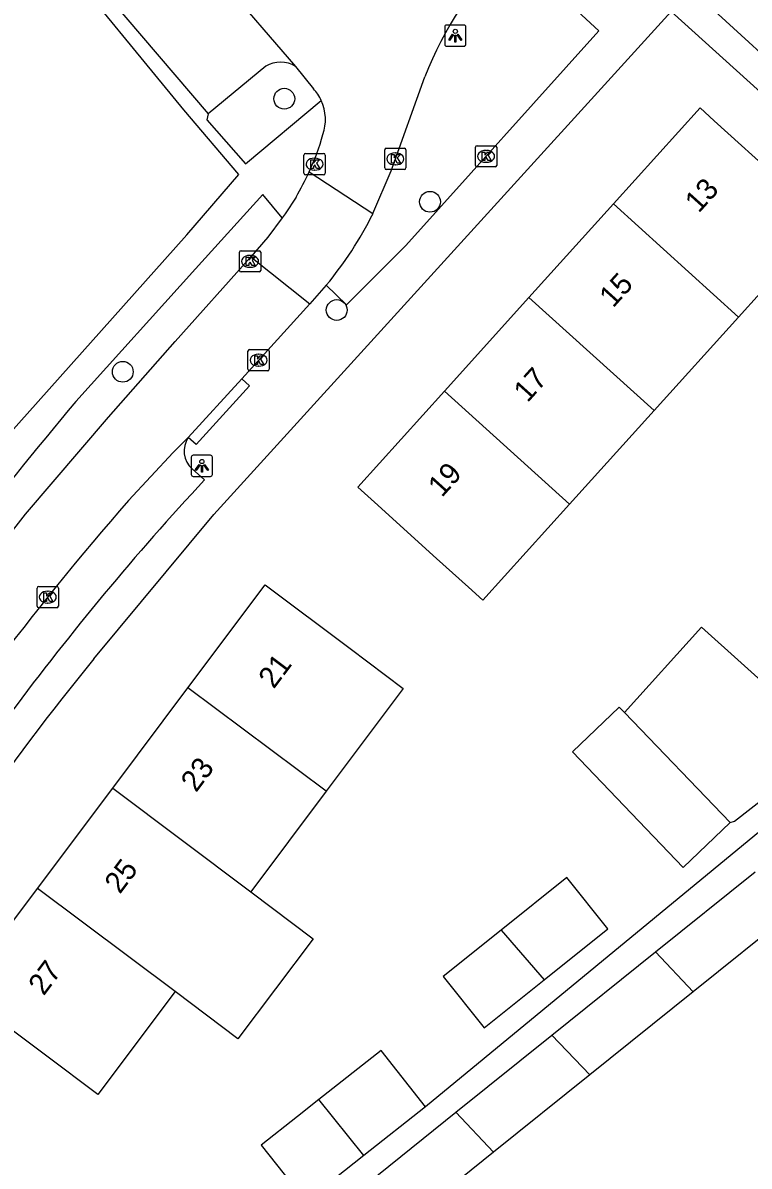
# Model space of a CAD drawing. Extents: x 161882 to 162509, y 381687 to 382379.
# Drawn here: x 162309.9 to 162344.1, y 381823.9 to 381877.6 of the extents above; entities that cross this region are included whole.
import ezdxf

# ---------------------------------------------------------------- set-up
doc = ezdxf.new("R2010")
doc.units = 0
for name, color, linetype in [('IMGEO_Boom', 7, 'Continuous'), ('IMGEO_Kolk', 7, 'Continuous'), ('IMGEO_Lichtpunt', 7, 'Continuous'), ('IMGEO_Pand', 7, 'Continuous'), ('IMGEO_Pand_nummerreeks', 7, 'Continuous'), ('IMGEO_Parkeervlak_open', 7, 'Continuous'), ('IMGEO_Rijbaan_lokaal_open', 7, 'Continuous'), ('IMGEO_Voetpad_open', 7, 'Continuous')]:
    doc.layers.add(name, color=color, linetype=linetype)

msp = doc.modelspace()

# ---------------------------------------------------------------- linework, layer by layer
at = {"layer": 'IMGEO_Boom'}
for centre in [(162322.227, 381874.072), (162329.077, 381869.231), (162324.693, 381864.143), (162314.637, 381861.242)]:
    msp.add_circle(centre, 0.489, dxfattribs=at)
at = {"layer": 'IMGEO_Kolk'}
for p, q in [((162326.947, 381870.819), (162326.947, 381871.671)), ((162327.022, 381871.745), (162327.874, 381871.745)), ((162327.948, 381871.671), (162327.948, 381870.819)), ((162331.214, 381870.94), (162331.214, 381871.792)), ((162331.289, 381871.866), (162332.141, 381871.866)), ((162331.702, 381871.646), (162331.727, 381871.646)), ((162332.215, 381871.792), (162332.215, 381870.94)), ((162323.151, 381870.571), (162323.151, 381871.423)), ((162323.226, 381871.497), (162324.078, 381871.497)), ((162323.639, 381871.277), (162323.664, 381871.277)), ((162324.152, 381871.423), (162324.152, 381870.571)), ((162327.435, 381871.525), (162327.46, 381871.525)), ((162331.725, 381871.086), (162331.7, 381871.086)), ((162324.078, 381870.497), (162323.226, 381870.497)), ((162323.662, 381870.717), (162323.637, 381870.717)), ((162327.874, 381870.745), (162327.022, 381870.745)), ((162327.458, 381870.965), (162327.433, 381870.965)), ((162332.141, 381870.866), (162331.289, 381870.866)), ((162320.119, 381866.006), (162320.119, 381866.858)), ((162320.194, 381866.932), (162321.046, 381866.932)), ((162320.607, 381866.712), (162320.632, 381866.712)), ((162321.12, 381866.858), (162321.12, 381866.006)), ((162321.046, 381865.932), (162320.194, 381865.932)), ((162320.63, 381866.152), (162320.605, 381866.152)), ((162320.52, 381861.36), (162320.52, 381862.212)), ((162320.595, 381862.286), (162321.447, 381862.286)), ((162321.008, 381862.066), (162321.033, 381862.066)), ((162321.521, 381862.212), (162321.521, 381861.36)), ((162321.031, 381861.506), (162321.006, 381861.506)), ((162321.447, 381861.286), (162320.595, 381861.286)), ((162310.685, 381851.154), (162311.537, 381851.154)), ((162310.61, 381850.228), (162310.61, 381851.08)), ((162311.098, 381850.934), (162311.123, 381850.934)), ((162311.611, 381851.08), (162311.611, 381850.228)), ((162311.537, 381850.154), (162310.685, 381850.154)), ((162311.121, 381850.374), (162311.096, 381850.374))]:
    msp.add_line(p, q, dxfattribs=at)
for points in [[(162326.947, 381870.819), (162326.947, 381871.671)], [(162327.022, 381871.745), (162327.874, 381871.745)], [(162327.948, 381871.671), (162327.948, 381870.819)], [(162331.214, 381870.94), (162331.214, 381871.792)], [(162331.289, 381871.866), (162332.141, 381871.866)], [(162331.535, 381871.566), (162331.658, 381871.566), (162331.658, 381871.415), (162331.788, 381871.566), (162331.952, 381871.566), (162331.806, 381871.415), (162331.959, 381871.166), (162331.807, 381871.166), (162331.722, 381871.33), (162331.658, 381871.263), (162331.658, 381871.166), (162331.535, 381871.166), (162331.535, 381871.566)], [(162332.215, 381871.792), (162332.215, 381870.94)], [(162323.151, 381870.571), (162323.151, 381871.423)], [(162323.226, 381871.497), (162324.078, 381871.497)], [(162323.472, 381871.197), (162323.595, 381871.197), (162323.595, 381871.046), (162323.725, 381871.197), (162323.889, 381871.197), (162323.743, 381871.046), (162323.896, 381870.797), (162323.744, 381870.797), (162323.659, 381870.961), (162323.595, 381870.894), (162323.595, 381870.797), (162323.472, 381870.797), (162323.472, 381871.197)], [(162324.152, 381871.423), (162324.152, 381870.571)], [(162327.268, 381871.445), (162327.391, 381871.445), (162327.391, 381871.294), (162327.521, 381871.445), (162327.685, 381871.445), (162327.539, 381871.294), (162327.692, 381871.045), (162327.54, 381871.045), (162327.455, 381871.209), (162327.391, 381871.142), (162327.391, 381871.045), (162327.268, 381871.045), (162327.268, 381871.445)], [(162324.078, 381870.497), (162323.226, 381870.497)], [(162327.874, 381870.745), (162327.022, 381870.745)], [(162332.141, 381870.866), (162331.289, 381870.866)], [(162320.119, 381866.006), (162320.119, 381866.858)], [(162320.194, 381866.932), (162321.046, 381866.932)], [(162321.12, 381866.858), (162321.12, 381866.006)], [(162320.44, 381866.632), (162320.563, 381866.632), (162320.563, 381866.481), (162320.693, 381866.632), (162320.857, 381866.632), (162320.711, 381866.481), (162320.864, 381866.232), (162320.712, 381866.232), (162320.627, 381866.396), (162320.563, 381866.329), (162320.563, 381866.232), (162320.44, 381866.232), (162320.44, 381866.632)], [(162321.046, 381865.932), (162320.194, 381865.932)], [(162320.52, 381861.36), (162320.52, 381862.212)], [(162320.595, 381862.286), (162321.447, 381862.286)], [(162320.841, 381861.986), (162320.964, 381861.986), (162320.964, 381861.835), (162321.094, 381861.986), (162321.258, 381861.986), (162321.112, 381861.835), (162321.265, 381861.586), (162321.113, 381861.586), (162321.028, 381861.75), (162320.964, 381861.683), (162320.964, 381861.586), (162320.841, 381861.586), (162320.841, 381861.986)], [(162321.521, 381862.212), (162321.521, 381861.36)], [(162321.447, 381861.286), (162320.595, 381861.286)], [(162310.685, 381851.154), (162311.537, 381851.154)], [(162310.61, 381850.228), (162310.61, 381851.08)], [(162310.931, 381850.854), (162311.054, 381850.854), (162311.054, 381850.703), (162311.184, 381850.854), (162311.348, 381850.854), (162311.202, 381850.703), (162311.355, 381850.454), (162311.203, 381850.454), (162311.118, 381850.618), (162311.054, 381850.551), (162311.054, 381850.454), (162310.931, 381850.454), (162310.931, 381850.854)], [(162311.611, 381851.08), (162311.611, 381850.228)], [(162311.537, 381850.154), (162310.685, 381850.154)]]:
    msp.add_lwpolyline(points, dxfattribs=at)
for centre, start, end in [((162327.024, 381871.669), 91.552, 178.448), ((162327.024, 381871.669), 91.552, 178.448), ((162327.872, 381871.669), 1.552, 88.448), ((162327.872, 381871.669), 1.552, 88.448), ((162331.291, 381871.79), 91.552, 178.448), ((162331.291, 381871.79), 91.552, 178.448), ((162332.139, 381871.79), 1.552, 88.448), ((162332.139, 381871.79), 1.552, 88.448), ((162323.228, 381871.421), 91.552, 178.448), ((162323.228, 381871.421), 91.552, 178.448), ((162324.076, 381871.421), 1.552, 88.448), ((162324.076, 381871.421), 1.552, 88.448), ((162323.228, 381870.573), 181.552, 268.448), ((162323.228, 381870.573), 181.552, 268.448), ((162324.076, 381870.573), 271.552, 358.448), ((162324.076, 381870.573), 271.552, 358.448), ((162327.024, 381870.821), 181.552, 268.448), ((162327.024, 381870.821), 181.552, 268.448), ((162327.872, 381870.821), 271.552, 358.448), ((162327.872, 381870.821), 271.552, 358.448), ((162331.291, 381870.942), 181.552, 268.448), ((162331.291, 381870.942), 181.552, 268.448), ((162332.139, 381870.942), 271.552, 358.448), ((162332.139, 381870.942), 271.552, 358.448), ((162320.196, 381866.856), 91.552, 178.448), ((162320.196, 381866.856), 91.552, 178.448), ((162321.044, 381866.856), 1.552, 88.448), ((162321.044, 381866.856), 1.552, 88.448), ((162320.196, 381866.008), 181.552, 268.448), ((162320.196, 381866.008), 181.552, 268.448), ((162321.044, 381866.008), 271.552, 358.448), ((162321.044, 381866.008), 271.552, 358.448), ((162320.597, 381862.21), 91.552, 178.448), ((162320.597, 381862.21), 91.552, 178.448), ((162321.445, 381862.21), 1.552, 88.448), ((162321.445, 381862.21), 1.552, 88.448), ((162320.597, 381861.362), 181.552, 268.448), ((162320.597, 381861.362), 181.552, 268.448), ((162321.445, 381861.362), 271.552, 358.448), ((162321.445, 381861.362), 271.552, 358.448), ((162310.687, 381851.078), 91.552, 178.448), ((162310.687, 381851.078), 91.552, 178.448), ((162311.535, 381851.078), 1.552, 88.448), ((162311.535, 381851.078), 1.552, 88.448), ((162310.687, 381850.23), 181.552, 268.448), ((162310.687, 381850.23), 181.552, 268.448), ((162311.535, 381850.23), 271.552, 358.448), ((162311.535, 381850.23), 271.552, 358.448)]:
    msp.add_arc(centre, 0.0765, start, end, dxfattribs=at)
for centre, major_axis, ratio, start_param, end_param in [((162331.701, 381871.366), (-0.387, 0.002), 0.722429, 4.712389, 7.853982), ((162331.726, 381871.366), (-0.39, 0.002), 0.717154, 1.570796, 4.712389), ((162323.638, 381870.997), (-0.387, 0.002), 0.722429, 4.712389, 7.853982), ((162323.663, 381870.997), (-0.39, 0.002), 0.717154, 1.570796, 4.712389), ((162327.434, 381871.245), (-0.387, 0.002), 0.722429, 4.712389, 7.853982), ((162327.459, 381871.245), (-0.39, 0.002), 0.717154, 1.570796, 4.712389), ((162320.606, 381866.432), (-0.387, 0.002), 0.722429, 4.712389, 7.853982), ((162320.631, 381866.432), (-0.39, 0.002), 0.717154, 1.570796, 4.712389), ((162321.007, 381861.786), (-0.387, 0.002), 0.722429, 4.712389, 7.853982), ((162321.032, 381861.786), (-0.39, 0.002), 0.717154, 1.570796, 4.712389), ((162311.097, 381850.654), (-0.387, 0.002), 0.722429, 4.712389, 7.853982), ((162311.122, 381850.654), (-0.39, 0.002), 0.717154, 1.570796, 4.712389)]:
    msp.add_ellipse(centre, major_axis=major_axis, ratio=ratio, start_param=start_param, end_param=end_param, dxfattribs=at)
at = {"layer": 'IMGEO_Lichtpunt'}
for p, q in [((162330.671, 381877.535), (162329.863, 381877.535)), ((162330.671, 381877.535), (162329.863, 381877.535)), ((162329.769, 381877.44), (162329.769, 381876.633)), ((162329.769, 381877.44), (162329.769, 381876.633)), ((162330.765, 381876.633), (162330.765, 381877.44)), ((162330.765, 381876.633), (162330.765, 381877.44)), ((162329.863, 381876.539), (162330.671, 381876.539)), ((162329.863, 381876.539), (162330.671, 381876.539)), ((162317.855, 381857.225), (162317.855, 381856.418)), ((162317.855, 381857.225), (162317.855, 381856.418)), ((162318.757, 381857.32), (162317.949, 381857.32)), ((162318.757, 381857.32), (162317.949, 381857.32)), ((162318.851, 381856.418), (162318.851, 381857.225)), ((162318.851, 381856.418), (162318.851, 381857.225)), ((162317.949, 381856.324), (162318.757, 381856.324)), ((162317.949, 381856.324), (162318.757, 381856.324))]:
    msp.add_line(p, q, dxfattribs=at)
for points in [[(162330.143, 381877.104), (162330.182, 381877.076), (162329.994, 381876.814), (162329.956, 381876.841), (162330.143, 381877.104)], [(162330.245, 381877.056), (162330.292, 381877.056), (162330.292, 381876.734), (162330.245, 381876.734), (162330.245, 381877.056)], [(162330.355, 381877.076), (162330.393, 381877.103), (162330.58, 381876.841), (162330.541, 381876.813), (162330.355, 381877.076)], [(162318.229, 381856.889), (162318.268, 381856.861), (162318.08, 381856.599), (162318.042, 381856.626), (162318.229, 381856.889)], [(162318.331, 381856.841), (162318.378, 381856.841), (162318.378, 381856.519), (162318.331, 381856.519), (162318.331, 381856.841)], [(162318.441, 381856.861), (162318.479, 381856.888), (162318.666, 381856.626), (162318.627, 381856.598), (162318.441, 381856.861)]]:
    msp.add_lwpolyline(points, dxfattribs=at)
for centre in [(162330.268, 381877.238), (162318.354, 381857.023)]:
    msp.add_circle(centre, 0.0994, dxfattribs=at)
for centre, start, end in [((162329.863, 381877.44), 90, 180), ((162329.863, 381877.44), 90, 180), ((162330.671, 381877.44), 0, 90), ((162330.671, 381877.44), 0, 90), ((162329.863, 381876.633), 180, 270), ((162329.863, 381876.633), 180, 270), ((162330.671, 381876.633), 270, 0), ((162330.671, 381876.633), 270, 360), ((162317.949, 381857.225), 90, 180), ((162317.949, 381857.225), 90, 180), ((162318.757, 381857.225), 0, 90), ((162318.757, 381857.225), 0, 90), ((162317.949, 381856.418), 180, 270), ((162317.949, 381856.418), 180, 270), ((162318.757, 381856.418), 270, 0), ((162318.757, 381856.418), 270, 360)]:
    msp.add_arc(centre, 0.0946, start, end, dxfattribs=at)
at = {"layer": 'IMGEO_Pand'}
for points in [[(162337.705, 381869.126), (162341.782, 381873.637), (162342.442, 381873.04), (162345.491, 381870.284), (162347.661, 381868.323), (162343.586, 381863.815)], [(162333.73, 381864.728), (162337.705, 381869.126)], [(162343.586, 381863.815), (162337.705, 381869.126)], [(162329.755, 381860.33), (162333.73, 381864.728)], [(162333.73, 381864.728), (162339.611, 381859.416)], [(162343.586, 381863.815), (162339.611, 381859.416)], [(162335.637, 381855.019), (162331.56, 381850.508), (162330.885, 381851.118), (162329.39, 381852.469), (162326.468, 381855.111), (162325.681, 381855.822), (162329.755, 381860.33)], [(162335.637, 381855.019), (162329.755, 381860.33)], [(162339.611, 381859.416), (162335.637, 381855.019)], [(162317.701, 381846.396), (162321.328, 381851.233), (162325.328, 381848.233), (162327.821, 381846.363), (162324.194, 381841.527)], [(162345.728, 381845.749), (162341.835, 381849.242), (162338.218, 381845.23)], [(162314.163, 381841.68), (162317.701, 381846.396)], [(162324.194, 381841.527), (162317.701, 381846.396)], [(162338.218, 381845.23), (162337.976, 381845.482), (162335.78, 381843.375), (162340.985, 381837.949), (162343.181, 381840.056)], [(162343.181, 381840.056), (162338.218, 381845.23)], [(162343.181, 381840.056), (162343.385, 381840.124), (162347.592, 381843.394)], [(162310.626, 381836.963), (162314.163, 381841.68)], [(162314.163, 381841.68), (162320.657, 381836.81)], [(162324.194, 381841.527), (162320.657, 381836.81)], [(162339.67, 381833.983), (162344.356, 381837.75)], [(162334.447, 381832.668), (162337.444, 381835.066), (162335.512, 381837.481), (162332.417, 381835.005)], [(162317.092, 381832.114), (162313.465, 381827.278), (162310.999, 381829.127), (162306.999, 381832.127), (162310.626, 381836.963)], [(162317.092, 381832.114), (162310.626, 381836.963)], [(162320.657, 381836.81), (162323.58, 381834.6), (162320.051, 381829.895), (162317.092, 381832.114)], [(162346.13, 381835.868), (162341.444, 381832.1)], [(162332.417, 381835.005), (162329.689, 381832.822), (162331.62, 381830.407), (162334.447, 381832.668)], [(162332.417, 381835.005), (162334.447, 381832.668)], [(162334.797, 381830.064), (162339.67, 381833.983)], [(162341.444, 381832.1), (162339.67, 381833.983)], [(162341.444, 381832.1), (162336.598, 381828.204)], [(162330.296, 381826.446), (162334.797, 381830.064)], [(162334.797, 381830.064), (162336.598, 381828.204)], [(162328.871, 381826.707), (162326.779, 381829.352), (162323.856, 381827.039)], [(162336.598, 381828.204), (162332.07, 381824.564)], [(162323.856, 381827.039), (162322.854, 381826.247), (162321.148, 381824.898), (162323.239, 381822.253)], [(162325.971, 381824.413), (162323.856, 381827.039)], [(162325.609, 381822.678), (162330.296, 381826.446)], [(162328.871, 381826.707), (162325.971, 381824.413)], [(162330.296, 381826.446), (162332.07, 381824.564)], [(162325.971, 381824.413), (162323.239, 381822.253)], [(162332.07, 381824.564), (162327.383, 381820.796)]]:
    msp.add_lwpolyline(points, dxfattribs=at)
at = {"layer": 'IMGEO_Parkeervlak_open'}
msp.add_lwpolyline([(162321.355, 381875.602), (162318.649, 381873.357)], dxfattribs=at)
msp.add_arc((162322.046, 381874.442), 1.35, 58.173, 120.7653, dxfattribs=at)
at = {"layer": 'IMGEO_Rijbaan_lokaal_open'}
for points in [[(162315.826, 381883.619), (162322.758, 381875.589)], [(162322.758, 381875.589), (162323.599, 381874.542)], [(162326.398, 381868.679), (162327.245, 381870.683), (162328.833, 381875.105)], [(162323.403, 381870.644), (162326.398, 381868.679)], [(162322.78, 381869.453), (162322.262, 381868.661), (162322.127, 381868.477)], [(162322.127, 381868.477), (162321.455, 381867.563), (162320.649, 381866.638)], [(162303.292, 381845.82), (162306.611, 381850.151), (162310.057, 381854.543), (162313.959, 381859.114), (162317.095, 381862.667), (162320.649, 381866.638)], [(162320.649, 381866.638), (162323.422, 381864.435)], [(162324.203, 381865.309), (162323.422, 381864.435)], [(162323.422, 381864.435), (162320.231, 381860.917)], [(162317.714, 381858.155), (162320.231, 381860.917)], [(162317.714, 381858.155), (162316.997, 381857.442), (162314.904, 381855.188)]]:
    msp.add_lwpolyline(points, dxfattribs=at)
for centre, radius, start, end in [((162345.092, 381868.706), 17.473, 134.6115, 158.5177), ((162322.041, 381873.109), 2.117, 24.4976, 42.5961), ((162322.02, 381873.094), 2.142, 340.8143, 24.6349), ((162312.483, 381875.637), 12.008, 335.4284, 344.3105), ((162311.472, 381876.126), 13.13, 329.4524, 335.3204), ((162310.747, 381876.474), 17.485, 320.3183, 333.5265), ((162424.966, 381759.231), 146.019, 138.91675, 147.00635)]:
    msp.add_arc(centre, radius, start, end, dxfattribs=at)
at = {"layer": 'IMGEO_Voetpad_open'}
for points in [[(162308.695, 381857.661), (162317.651, 381867.68), (162320.093, 381870.515), (162317.508, 381873.557), (162311.416, 381880.988), (162315.774, 381884.648), (162315.994, 381884.379), (162316.488, 381884.836)], [(162315.826, 381883.619), (162312.385, 381880.712), (162318.649, 381873.357)], [(162332.821, 381881.145), (162337.02, 381877.264), (162327.942, 381867.176), (162325.146, 381864.385), (162324.203, 381865.309)], [(162341.358, 381879.213), (162345.341, 381875.564)], [(162313.274, 381847.757), (162318.912, 381854.529), (162340.416, 381878.177)], [(162359.495, 381860.949), (162346.556, 381872.633), (162340.416, 381878.177)], [(162318.649, 381873.357), (162318.587, 381873.075), (162320.411, 381871.008), (162323.967, 381873.987)], [(162322.127, 381868.477), (162321.225, 381869.573), (162318.048, 381866.084), (162312.423, 381859.839)], [(162320.231, 381860.917), (162320.6, 381860.581), (162318.083, 381857.819), (162317.714, 381858.155)], [(162317.896, 381856.676), (162318.479, 381856.168)], [(162353.543, 381847.003), (162353.161, 381846.707), (162328.871, 381826.707)]]:
    msp.add_lwpolyline(points, dxfattribs=at)
for centre, radius, start, end in [((162591.617, 381627.062), 363.503, 140.18045, 142.96062), ((162318.634, 381857.517), 1.119, 145.2711, 228.7596), ((162415.221, 381766.452), 131.939, 137.15809, 143.35927), ((162413.302, 381766.264), 129.022, 140.83, 149.413)]:
    msp.add_arc(centre, radius, start, end, dxfattribs=at)

# ---------------------------------------------------------------- texts
at = {"layer": 'IMGEO_Pand_nummerreeks'}
for s, rotation, p in [('13', 47.8931, (162341.71, 381868.666)), ('15', 47.8931, (162337.685, 381864.212)), ('17', 47.8931, (162333.659, 381859.758)), ('19', 47.8931, (162329.634, 381855.304)), ('21', 53.1311, (162321.733, 381846.306)), ('23', 53.1311, (162318.083, 381841.439)), ('25', 53.1304, (162314.5, 381836.663)), ('27', 53.1311, (162310.918, 381831.886))]:
    msp.add_text(s, height=1, rotation=rotation, dxfattribs=at).set_placement(p)

doc.saveas('drawing.dxf')
